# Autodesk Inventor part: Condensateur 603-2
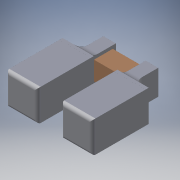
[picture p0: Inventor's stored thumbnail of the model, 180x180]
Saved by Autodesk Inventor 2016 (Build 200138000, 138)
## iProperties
Created: 2018-03
Part Number: Condensateur 603-2
Material: Générique
Document SubType Name: Modeling
Designer: Bruno
Density: 1 g/cm^3
Appearance: Par défaut
Author: Bruno
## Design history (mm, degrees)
feature "Composite1"
body "Srf1"
